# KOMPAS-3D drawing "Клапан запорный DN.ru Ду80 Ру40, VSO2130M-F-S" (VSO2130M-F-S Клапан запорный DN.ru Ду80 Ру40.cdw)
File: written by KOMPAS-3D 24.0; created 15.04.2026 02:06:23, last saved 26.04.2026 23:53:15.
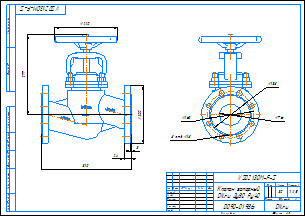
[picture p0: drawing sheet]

Document properties: Автор: DN.ru; Форматы листов документа: A3; Полное имя файла: VSO2130M-F-S Клапан запорный DN.ru Ду80 Ру40.m3d; Масса: 30; Наименование: Клапан запорный DN.ru Ду80 Ру40; Количество листов документа: 1; Примечание: D090-01986

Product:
- Part/product: Клапан запорный DN.ru Ду80 Ру40  | designation VSO2130M-F-S
    Масса: 30
    Раздел спецификации: Прочие изделия
    Примечание: D090-01986

Views: Вид 1, Вид:1, Проекционный вид 2
Referenced files in C:\Работа\VSO2130M-F-S Клапан запорный DN.ru\DN20\: VSO2130M-F-S DN20 PN40  Клапан запорный сильфонный DN.ru.m3d
Referenced files in C:\Работа\VSO2130M-F-S Клапан запорный DN.ru\DN80\: VSO2130M-F-S Клапан запорный DN.ru Ду80 Ру40.m3d
Referenced files in C:\Program Files\ASCON\KOMPAS-3D v24\Templates\: Чертеж_DN.ru.cdt
Referenced files in C:\Работа\ГОТОВЫЕ ИСХОДНИКИ\VSO2130M-F-S Клапан запорный сальниковый DN.ru Ду15-100 Ру40\DN80\: VSO2130M-F-S Клапан запорный DN.ru Ду80 Ру40.m3d
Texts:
  VSO2130M-F-S
  Чертеж_DN.ru.cdt
  Клапан запорный
  DN.ru Ду80 Ру40
  Клапан запорный DN.ru Ду80 Ру40
  VSO2130M-F-S Клапан запорный DN.ru Ду80 Ру40
Dimensions and other numbers on the sheet: 0; 3; 2; 4; 200; 310; 24; 277; 220; 5; 76; 138; 160; 8 отв.; 18; 1:2,5; 1; 30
